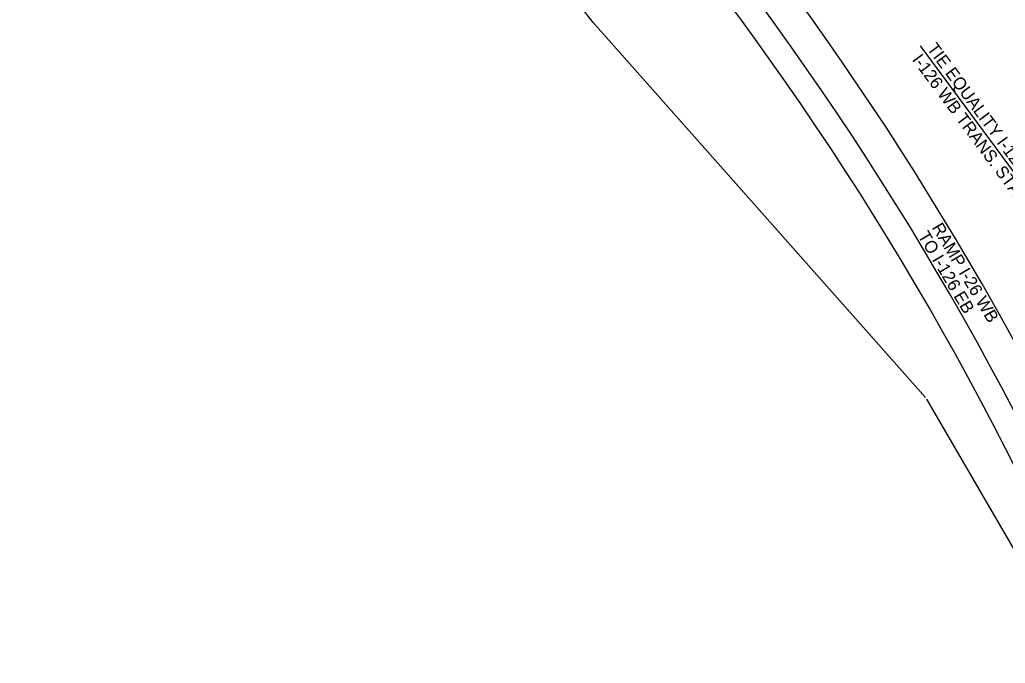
# Model space of a CAD drawing. Extents: x 1966090 to 1975830, y 788086 to 801233.
# Drawn here: x 1969763.6 to 1970241, y 796789.9 to 797101.7 of the extents above; entities that cross this region are included whole.
import ezdxf

# ---------------------------------------------------------------- set-up
doc = ezdxf.new("R2010")
doc.units = 0
for name, color, linetype in [('BR_REBAR', 7, 'Continuous'), ('RD_EX_SU_Gas', 7, 'Continuous'), ('RD_EX_SU_H2O', 7, 'Continuous'), ('RD_EX_TX_Dam_ELEV', 7, 'Continuous'), ('RD_PD_PaveShd', 7, 'Continuous'), ('RD_Sketch6', 7, 'Continuous'), ('RD_Sketch8', 7, 'Continuous'), ('RD_Sketch9', 7, 'Continuous')]:
    doc.layers.add(name, color=color, linetype=linetype)

msp = doc.modelspace()

# ---------------------------------------------------------------- linework, layer by layer
at = {"layer": 'BR_REBAR'}
msp.add_arc((1963181.81, 792525.99), 8429, 31.397656, 33.871644, dxfattribs=at)
at = {"layer": 'RD_EX_SU_Gas'}
for centre, radius, end in [((1958843.44, 788350.87), 14500, 39.566224), ((1958843.44, 788350.87), 14488, 39.566224), ((1961201.85, 790089.49), 11512, 39.351802), ((1961201.85, 790089.49), 11500, 39.351802)]:
    msp.add_arc(centre, radius, 36.397656, end, dxfattribs=at)
at = {"layer": 'RD_EX_TX_Dam_ELEV'}
for p, q in [((1970041.43, 797100.34), (1970202.43, 796918.59)), ((1970277.33, 796789.87), (1970203.01, 796917.79))]:
    msp.add_line(p, q, dxfattribs=at)
msp.add_arc((1968885.76, 796201.61), 1464, 37.87079, 49.76906, dxfattribs=at)
at = {"layer": 'RD_PD_PaveShd'}
for centre, radius, start, end in [((1968885.76, 796201.61), 1522, 23.63926, 54.77615), ((1963181.81, 792525.99), 8430, 31.397656, 34.6698)]:
    msp.add_arc(centre, radius, start, end, dxfattribs=at)
at = {"layer": 'RD_Sketch6'}
msp.add_line((1970296.39, 796958.41), (1970200.01, 797089.15), dxfattribs=at)
at = {"layer": 'RD_Sketch8'}
for centre, radius, start, end in [((1958843.44, 788350.87), 14476, 36.397656, 39.566224), ((1968885.76, 796201.61), 1550, 24.69023, 54.77615), ((1968885.76, 796201.61), 1534, 23.63926, 54.77615), ((1961201.85, 790089.49), 11524, 36.397656, 39.351802), ((1963181.81, 792525.99), 8440, 31.397656, 34.6724)]:
    msp.add_arc(centre, radius, start, end, dxfattribs=at)
at = {"layer": 'RD_Sketch9'}
for centre, radius, end in [((1958787.09, 788309.34), 14534, 39.713887), ((1958843.44, 788350.87), 14466, 39.566224)]:
    msp.add_arc(centre, radius, 36.397656, end, dxfattribs=at)

# ---------------------------------------------------------------- texts
at = {"layer": 'RD_EX_SU_H2O'}
for s, p in [('RAMP I-26 WB ', (1970205.23, 797001.04)), ('TO I-126 EB ', (1970198.47, 796997.02))]:
    msp.add_text(s, height=5.9996, rotation=300.7307, dxfattribs=at).set_placement(p)
at = {"layer": 'RD_Sketch6'}
for s, p in [('TIE EQUALITY I-126 STA. 21+50.00 =', (1970202.83, 797087.67)), ("I-126 WB TRANS. STA. 21+50.00 35.00' LT", (1970195.6, 797082.31))]:
    msp.add_text(s, height=5.9996, rotation=306.5592, dxfattribs=at).set_placement(p)

doc.saveas('drawing.dxf')
